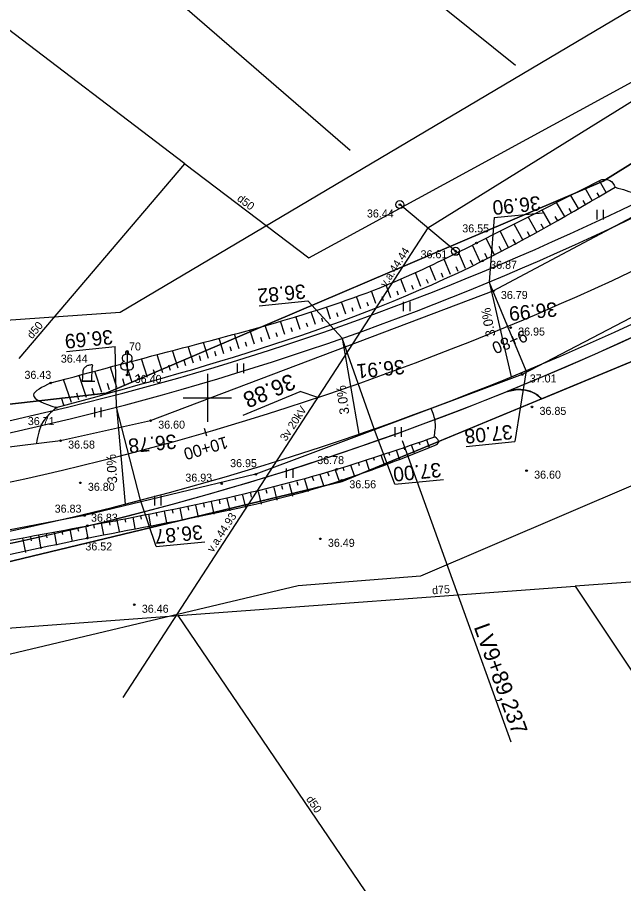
# Model space of a CAD drawing. Extents: x 469981 to 472086, y 246785 to 247785.
# Drawn here: x 471088.1 to 471126, y 247169.7 to 247223.8 of the extents above; entities that cross this region are included whole.
import ezdxf

# ---------------------------------------------------------------- set-up
doc = ezdxf.new("R2010")
doc.units = 0
for name, color, linetype in [('0_922', 7, 'Continuous'), ('0_Asfalta_mala', 7, 'Continuous'), ('0_Asfalta_Nomale', 7, 'Continuous'), ('0_Ruut_Braukt', 7, 'Continuous'), ('0_Ruut_nomale', 7, 'Continuous'), ('0_Ruutojums_Nobrauktuves_pieslegumi', 7, 'Continuous'), ('0_vertikals', 7, 'Continuous'), ('0_Vertikals_SavietotieInztikli', 7, 'Continuous'), ('0_vertkals_cipari', 7, 'Continuous'), ('21', 7, 'Continuous'), ('5_patagas', 7, 'Continuous'), ('6_piketaza', 7, 'Continuous'), ('CELI_CMAL_####_####_#', 7, 'Continuous'), ('DREN_VADP_####_####_#', 7, 'Continuous'), ('DREN_VADP_####_TKST_#', 7, 'Continuous'), ('DREN_VADP_KLKT_####_#', 7, 'Continuous'), ('DREN_VADP_KLKT_TKST_#', 7, 'Continuous'), ('ELEK_ELEM_####_####_#', 7, 'Continuous'), ('ELEK_SAVL_####_####_#', 7, 'Continuous'), ('ELEK_VADV_VSPR_####_#', 7, 'Continuous'), ('ELEK_VADV_VSPR_TKST_#', 7, 'Continuous'), ('GEOD_ELEM_####_####_#', 7, 'Continuous'), ('RAMI_UZMR_####_####_#', 7, 'Continuous'), ('RELJ_AATZ_####_TKST_#', 7, 'Continuous'), ('RELJ_ELEM_####_####_#', 7, 'Continuous'), ('RELJ_NOGA_####_####_#', 7, 'Continuous'), ('RELJ_NOGL_####_####_#', 7, 'Continuous'), ('ROBZ_IERR_####_####_#', 7, 'Continuous'), ('ROBZ_PROJ_####_####_#', 7, 'Continuous'), ('ROBZ_UZMR_####_####_#', 7, 'Continuous'), ('TERT_DIAM_####_TKST_#', 7, 'Continuous'), ('TERT_ELEM_####_####_#', 7, 'Continuous'), ('TERT_KONT_####_####_#', 7, 'Continuous')]:
    doc.layers.add(name, color=color, linetype=linetype)

msp = doc.modelspace()

# ---------------------------------------------------------------- linework, layer by layer
at = {"layer": '0_922'}
msp.add_arc((471049.697, 247370.7), 180, 277.44649, 302.18491, dxfattribs=at)
at = {"layer": '0_Asfalta_mala'}
for radius in [177, 183]:
    msp.add_arc((471049.697, 247370.7), radius, 277.44649, 302.18491, dxfattribs=at)
at = {"layer": '0_Asfalta_Nomale'}
for centre, radius, start, end in [((471049.697, 247370.7), 176.25, 277.44649, 302.18491), ((471049.697, 247370.7), 183.75, 277.44649, 292.06313), ((471119.477, 247198.533), 2, 45.236, 112.0499)]:
    msp.add_arc(centre, radius, start, end, dxfattribs=at)
at = {"layer": '0_Ruut_Braukt'}
for radius in [177, 183]:
    msp.add_arc((471049.697, 247370.7), radius, 277.44649, 302.18491, dxfattribs=at)
at = {"layer": '0_Ruut_nomale'}
for radius in [176.25, 177, 183, 183.75]:
    msp.add_arc((471049.697, 247370.7), radius, 277.44649, 302.18491, dxfattribs=at)
at = {"layer": '0_Ruutojums_Nobrauktuves_pieslegumi'}
msp.add_lwpolyline([(471126.647, 247202.343), (471126.642, 247202.698), (471126.793, 247203.326), (471127.142, 247203.879), (471127.778, 247204.365), (471126.081, 247203.579), (471124.175, 247202.721), (471122.812, 247202.123), (471120.922, 247201.316), (471118.719, 247200.406), (471119.354, 247200.529), (471119.871, 247200.494), (471120.234, 247200.385), (471120.541, 247200.227), (471120.886, 247199.953)], close=True, dxfattribs=at)
at = {"layer": '0_vertikals'}
for p, q in [((471117.907, 247211.264), (471117.603, 247207.245)), ((471117.907, 247211.264), (471120.938, 247211.569)), ((471103.241, 247205.754), (471106.272, 247206.059)), ((471108.421, 247203.726), (471106.272, 247206.059)), ((471091.204, 247202.907), (471094.236, 247203.211)), ((471094.32, 247199.417), (471094.236, 247203.211)), ((471119.905, 247201.704), (471119.194, 247197.275)), ((471111.706, 247194.605), (471110.411, 247198.066)), ((471116.163, 247196.971), (471119.194, 247197.275)), ((471111.706, 247194.605), (471114.737, 247194.909)), ((471096.812, 247190.713), (471095.832, 247193.611)), ((471096.812, 247190.713), (471099.844, 247191.018))]:
    msp.add_line(p, q, dxfattribs=at)
for points in [[(471117.603, 247207.245), (471118.981, 247201.322), (471119.905, 247201.704)], [(471108.421, 247203.726), (471109.467, 247197.736), (471110.411, 247198.066)], [(471094.32, 247199.417), (471094.864, 247193.361), (471095.832, 247193.611)]]:
    msp.add_lwpolyline(points, close=True, dxfattribs=at)
at = {"layer": '0_Vertikals_SavietotieInztikli'}
for p in [(471102.247, 247198.915), (471106.891, 247200.028)]:
    msp.add_line(p, (471105.797, 247200.401), dxfattribs=at)
at = {"layer": '21'}
msp.add_arc((471049.697, 247370.7), 180, 277.44649, 302.18491, dxfattribs=at)
at = {"layer": '5_patagas'}
msp.add_lwpolyline([(471112.166, 247197.334), (471118.946, 247178.518)], dxfattribs=at)
at = {"layer": '6_piketaza'}
for points in [[(471118.85, 247204.243), (471118.658, 247204.705)], [(471099.966, 247197.602), (471099.827, 247198.082)]]:
    msp.add_lwpolyline(points, dxfattribs=at)
at = {"layer": 'CELI_CMAL_####_####_#'}
for points in [[(471014.161, 247188.048), (471038.308, 247191.645), (471077.61, 247195.71), (471090.836, 247197.337), (471096.461, 247198.582), (471117.856, 247206.682), (471130.197, 247213.261), (471151.631, 247225.738), (471175.407, 247239.608), (471196.168, 247252.49), (471217.229, 247265.52), (471244.784, 247283.359), (471266.102, 247296.914), (471293.433, 247314.365), (471318.262, 247330.084), (471336.637, 247341.969), (471339.45, 247343.841), (471340.412, 247346.293), (471340.291, 247349.818), (471339.894, 247353.24), (471336.901, 247360.015), (471333.813, 247367.721)], [(471347.348, 247327.622), (471345.475, 247334.467), (471344.349, 247336.664), (471343.67, 247337.19), (471342.054, 247337.492), (471341.155, 247337.494), (471339.762, 247336.569), (471318.941, 247323.623), (471297.221, 247309.64), (471268.834, 247291.51), (471247.888, 247278.119), (471219.179, 247259.989), (471200.048, 247247.93), (471177.515, 247234.149), (471154.773, 247220.961), (471131.272, 247207.521), (471119.66, 247201.466), (471103.03, 247195.231), (471092.329, 247192.658), (471077.436, 247189.782), (471058.729, 247187.944), (471037.006, 247184.759), (471015.923, 247182.598), (470992.26, 247181.035)]]:
    msp.add_lwpolyline(points, dxfattribs=at)
at = {"layer": 'DREN_VADP_####_####_#'}
for points in [[(471093.793, 247241.252), (471119.237, 247220.794)], [(471098.595, 247214.62), (471106.329, 247208.745), (471138.491, 247226.277), (471152.344, 247233.828)], [(471088.246, 247202.471), (471098.595, 247214.62)], [(471151.231, 247181.956), (471145.953, 247189.907), (471122.964, 247188.241)], [(471122.964, 247188.241), (471132.872, 247173.374)], [(471113.256, 247164.203), (471098.172, 247186.404)]]:
    msp.add_lwpolyline(points, dxfattribs=at)
at = {"layer": 'DREN_VADP_KLKT_####_#'}
for points in [[(471108.928, 247215.461), (471082.698, 247238.164)], [(471098.595, 247214.62), (471086.597, 247223.736), (471071.652, 247235.09)], [(471004.84, 247177.619), (471029.945, 247181.347), (471052.991, 247183.055), (471075.414, 247184.717), (471098.172, 247186.404), (471122.964, 247188.241)]]:
    msp.add_lwpolyline(points, dxfattribs=at)
at = {"layer": 'ELEK_ELEM_####_####_#'}
for centre in [(471112.022, 247212.08), (471115.502, 247209.16)]:
    msp.add_circle(centre, 0.25, dxfattribs=at)
at = {"layer": 'ELEK_SAVL_####_####_#'}
msp.add_line((471115.502, 247209.16), (471112.022, 247212.08), dxfattribs=at)
at = {"layer": 'ELEK_VADV_VSPR_####_#'}
for q in [(471169.047, 247244.988), (471094.727, 247181.28)]:
    msp.add_line((471113.762, 247210.62), q, dxfattribs=at)
at = {"layer": 'GEOD_ELEM_####_####_#'}
for p, q in [((471100, 247201.5), (471100, 247200)), ((471098.5, 247200), (471100, 247200)), ((471100, 247200), (471100, 247198.5)), ((471100, 247200), (471101.5, 247200))]:
    msp.add_line(p, q, dxfattribs=at)
at = {"layer": 'RAMI_UZMR_####_####_#'}
for points in [[(471010.572, 247199.465), (471044.448, 247201.846), (471094.566, 247205.368), (471219.251, 247279.294), (471287.982, 247320.045), (471329.582, 247346.385), (471332.466, 247352.407), (471329.951, 247358.592), (471331.784, 247361.204), (471339.558, 247364.746), (471343.514, 247360.959), (471346.629, 247357.978), (471355.9, 247363.1), (471457.4, 247429.3)], [(471380.292, 247353.371), (471352.036, 247335.759), (471352.913, 247327.325), (471347.47, 247325.392), (471345.187, 247325.919), (471342.905, 247329.082), (471319.551, 247313.443), (471222.661, 247251.69), (471157.352, 247211.35), (471144.207, 247202.916), (471131.364, 247196.59), (471113.303, 247188.858), (471105.677, 247188.256), (471083.576, 247183.01), (471075.205, 247182.665), (471043.397, 247175.418), (471016.707, 247172.079), (470997.217, 247171.376)]]:
    msp.add_lwpolyline(points, dxfattribs=at)
at = {"layer": 'RELJ_ELEM_####_####_#'}
for centre in [(471112.022, 247212.08), (471116.807, 247209.683), (471115.502, 247209.16), (471117.19, 247208.567), (471117.856, 247206.682), (471118.936, 247204.398), (471094.992, 247201.437), (471119.66, 247201.466), (471090.221, 247200.936), (471090.563, 247199.396), (471120.27, 247199.442), (471096.461, 247198.582), (471090.836, 247197.337), (471108.077, 247195.543), (471119.933, 247195.459), (471103.03, 247195.231), (471108.392, 247194.857), (471092.068, 247194.698), (471100.896, 247194.639), (471092.329, 247192.658), (471092.52, 247192.014), (471092.506, 247191.243), (471107.056, 247191.2), (471095.436, 247187.08)]:
    msp.add_circle(centre, 0.05, dxfattribs=at)
at = {"layer": 'RELJ_NOGA_####_####_#'}
for p, q in [((471124.902, 247212.844), (471124.49, 247213.568)), ((471123.175, 247211.836), (471122.689, 247212.656)), ((471124.036, 247212.344), (471123.587, 247213.111)), ((471124.468, 247212.596), (471124.339, 247212.819)), ((471125.338, 247213.09), (471125.337, 247213.09)), ((471122.314, 247211.327), (471121.795, 247212.204)), ((471123.605, 247212.091), (471123.464, 247212.328)), ((471121.453, 247210.818), (471120.906, 247211.754)), ((471122.745, 247211.581), (471122.594, 247211.836)), ((471120.587, 247210.318), (471120.025, 247211.308)), ((471121.884, 247211.072), (471121.723, 247211.343)), ((471119.715, 247209.83), (471119.15, 247210.865)), ((471121.021, 247210.567), (471120.854, 247210.856)), ((471117.937, 247208.913), (471117.421, 247209.991)), ((471118.832, 247209.36), (471118.28, 247210.425)), ((471120.152, 247210.072), (471119.982, 247210.376)), ((471117.029, 247208.495), (471116.559, 247209.554)), ((471118.386, 247209.133), (471118.225, 247209.456)), ((471119.275, 247209.592), (471119.106, 247209.908)), ((471116.112, 247208.096), (471115.678, 247209.11)), ((471117.485, 247208.701), (471117.336, 247209.022)), ((471115.191, 247207.707), (471114.791, 247208.671)), ((471116.571, 247208.294), (471116.435, 247208.606)), ((471113.336, 247206.96), (471112.997, 247207.825)), ((471114.265, 247207.329), (471113.898, 247208.241)), ((471114.728, 247207.517), (471114.613, 247207.798)), ((471115.652, 247207.9), (471115.527, 247208.197)), ((471112.403, 247206.6), (471112.087, 247207.426)), ((471113.801, 247207.143), (471113.695, 247207.409)), ((471111.466, 247206.248), (471111.17, 247207.047)), ((471112.87, 247206.779), (471112.772, 247207.032)), ((471109.586, 247205.568), (471109.314, 247206.339)), ((471110.527, 247205.905), (471110.246, 247206.685)), ((471110.997, 247206.076), (471110.91, 247206.312)), ((471111.935, 247206.423), (471111.844, 247206.667)), ((471107.696, 247204.915), (471107.433, 247205.69)), ((471108.642, 247205.238), (471108.375, 247206.008)), ((471109.114, 247205.403), (471109.034, 247205.633)), ((471110.057, 247205.736), (471109.974, 247205.968)), ((471105.798, 247204.282), (471105.533, 247205.09)), ((471106.748, 247204.596), (471106.486, 247205.385)), ((471108.169, 247205.076), (471108.09, 247205.307)), ((471104.847, 247203.973), (471104.579, 247204.805)), ((471106.273, 247204.439), (471106.194, 247204.678)), ((471107.222, 247204.755), (471107.143, 247204.989)), ((471101.989, 247203.062), (471101.696, 247203.993)), ((471102.943, 247203.363), (471102.659, 247204.258)), ((471103.895, 247203.666), (471103.62, 247204.528)), ((471104.371, 247203.819), (471104.29, 247204.073)), ((471105.323, 247204.127), (471105.243, 247204.373)), ((471100.08, 247202.464), (471099.765, 247203.474)), ((471101.035, 247202.762), (471100.731, 247203.732)), ((471102.466, 247203.212), (471102.379, 247203.486)), ((471103.419, 247203.514), (471103.335, 247203.778)), ((471098.172, 247201.867), (471097.83, 247202.96)), ((471099.126, 247202.165), (471098.797, 247203.217)), ((471101.512, 247202.912), (471101.422, 247203.197)), ((471096.264, 247201.267), (471095.891, 247202.444)), ((471097.217, 247201.568), (471096.861, 247202.702)), ((471099.603, 247202.315), (471099.507, 247202.624)), ((471100.558, 247202.613), (471100.465, 247202.91)), ((471094.359, 247200.658), (471093.948, 247201.928)), ((471095.311, 247200.964), (471094.921, 247202.186)), ((471097.694, 247201.718), (471097.59, 247202.052)), ((471098.649, 247202.016), (471098.548, 247202.338)), ((471092.458, 247200.036), (471092.001, 247201.41)), ((471093.407, 247200.349), (471092.977, 247201.669)), ((471095.787, 247201.116), (471095.672, 247201.476)), ((471096.74, 247201.418), (471096.631, 247201.764)), ((471091.509, 247199.719), (471091.027, 247201.15)), ((471093.883, 247200.504), (471093.757, 247200.893)), ((471094.834, 247200.812), (471094.715, 247201.185)), ((471091.983, 247199.878), (471091.843, 247200.299)), ((471092.932, 247200.193), (471092.799, 247200.597)), ((471091.036, 247199.558), (471090.887, 247199.997)), ((471090.563, 247199.396), (471090.563, 247199.397)), ((471114.16, 247197.552), (471114.16, 247197.552)), ((471112.735, 247197.082), (471112.912, 247196.548)), ((471113.21, 247197.238), (471113.261, 247197.084)), ((471113.685, 247197.395), (471113.849, 247196.899)), ((471110.836, 247196.454), (471111.037, 247195.847)), ((471111.311, 247196.611), (471111.369, 247196.434)), ((471111.786, 247196.768), (471111.974, 247196.197)), ((471112.261, 247196.925), (471112.315, 247196.759)), ((471109.412, 247195.984), (471109.478, 247195.785)), ((471109.887, 247196.141), (471110.1, 247195.496)), ((471110.361, 247196.298), (471110.423, 247196.11)), ((471107.512, 247195.36), (471107.582, 247195.139)), ((471107.987, 247195.514), (471108.223, 247194.794)), ((471108.462, 247195.67), (471108.532, 247195.46)), ((471108.937, 247195.827), (471109.162, 247195.145)), ((471106.076, 247194.926), (471106.301, 247194.152)), ((471106.556, 247195.066), (471106.624, 247194.837)), ((471107.034, 247195.211), (471107.265, 247194.459)), ((471103.661, 247194.28), (471103.719, 247194.043)), ((471104.146, 247194.402), (471104.347, 247193.611)), ((471104.63, 247194.528), (471104.692, 247194.291)), ((471105.113, 247194.657), (471105.327, 247193.87)), ((471105.595, 247194.789), (471105.66, 247194.555)), ((471101.226, 247193.714), (471101.395, 247192.943)), ((471101.714, 247193.822), (471101.766, 247193.589)), ((471102.202, 247193.932), (471102.382, 247193.15)), ((471102.689, 247194.046), (471102.744, 247193.809)), ((471103.175, 247194.161), (471103.366, 247193.372)), ((471098.778, 247193.205), (471098.822, 247192.984)), ((471099.269, 247193.304), (471099.419, 247192.559)), ((471099.758, 247193.403), (471099.805, 247193.178)), ((471100.248, 247193.505), (471100.407, 247192.746)), ((471100.737, 247193.609), (471100.786, 247193.379)), ((471095.832, 247192.639), (471095.872, 247192.426)), ((471096.324, 247192.731), (471096.459, 247192.018)), ((471096.815, 247192.824), (471096.856, 247192.609)), ((471097.306, 247192.918), (471097.444, 247192.198)), ((471097.797, 247193.013), (471097.839, 247192.795)), ((471098.288, 247193.108), (471098.431, 247192.377)), ((471093.375, 247192.177), (471093.512, 247191.455)), ((471093.867, 247192.27), (471093.907, 247192.055)), ((471094.358, 247192.362), (471094.492, 247191.65)), ((471094.849, 247192.454), (471094.889, 247192.241)), ((471095.341, 247192.546), (471095.474, 247191.837)), ((471090.429, 247191.61), (471090.585, 247190.808)), ((471090.92, 247191.705), (471090.966, 247191.47)), ((471091.411, 247191.8), (471091.56, 247191.033)), ((471091.902, 247191.895), (471091.946, 247191.669)), ((471092.393, 247191.99), (471092.536, 247191.249)), ((471092.884, 247192.084), (471092.926, 247191.865)), ((471088.466, 247191.23), (471088.637, 247190.347)), ((471088.957, 247191.325), (471089.007, 247191.066)), ((471089.448, 247191.42), (471089.611, 247190.579)), ((471089.939, 247191.515), (471089.986, 247191.269))]:
    msp.add_line(p, q, dxfattribs=at)
for points in [[(471090.563, 247199.396), (471117.19, 247208.567), (471125.472, 247213.165)], [(471037.008, 247183.786), (471077.386, 247189.324), (471092.52, 247192.014), (471108.077, 247195.543), (471114.215, 247197.57)]]:
    msp.add_spline(points, degree=3, dxfattribs=at)
at = {"layer": 'RELJ_NOGL_####_####_#'}
for points in [[(471090.221, 247200.936), (471098.006, 247203.007), (471112.108, 247207.435), (471117.36, 247209.96), (471124.639, 247213.643)], [(471124.639, 247213.643), (471125.14, 247213.594), (471125.472, 247213.165)], [(471090.221, 247200.936), (471089.14, 247200.19), (471090.563, 247199.396)], [(471114.235, 247197.043), (471114.448, 247197.245), (471114.215, 247197.57)], [(471036.91, 247182.787), (471077.214, 247187.994), (471092.506, 247191.243), (471108.392, 247194.857), (471114.235, 247197.043)]]:
    msp.add_spline(points, degree=3, dxfattribs=at)
at = {"layer": 'ROBZ_IERR_####_####_#'}
msp.add_lwpolyline([(471513.259, 247488.166), (471524.883, 247464.852), (471341.261, 247348.2), (471124.72, 247213.54), (471093.674, 247200.298), (471050.609, 247195.379), (471001.509, 247189.266), (470977.922, 247249.601)], dxfattribs=at)
at = {"layer": 'ROBZ_PROJ_####_####_#'}
for points in [[(470613.752, 247179.765), (470688.303, 247197.106), (470783.692, 247219.293), (470809.088, 247224.67), (470845.751, 247226.447), (470876.169, 247225.296), (470921.641, 247209.731), (470967.353, 247194.084), (470989.48, 247188.802), (471001.509, 247189.266), (471050.609, 247195.379), (471093.674, 247200.298), (471124.72, 247213.54), (471341.261, 247348.2), (471524.883, 247464.852)], [(471398.351, 247372.094), (471346.741, 247338.478), (471133.176, 247205.05), (471108.425, 247194.786), (471087.339, 247189.709), (471023.306, 247181.157), (470962.604, 247185.245), (470905.63, 247205.857), (470878.75, 247214.454), (470852.344, 247217.039), (470815.743, 247215.147), (470778.583, 247209.26), (470718.669, 247194.633), (470636.973, 247175.147), (470468.364, 247124.23), (470431.624, 247112.202), (470396.219, 247097.502), (470371.503, 247083.47), (470275.956, 246992.729), (470152.342, 246907.761), (470066.737, 246851.23)]]:
    msp.add_lwpolyline(points, dxfattribs=at)
at = {"layer": 'ROBZ_UZMR_####_####_#'}
msp.add_lwpolyline([(470963.76, 247148.152), (470962.604, 247185.245), (471023.306, 247181.157), (471087.339, 247189.709), (471108.425, 247194.786), (471133.176, 247205.05), (471165.539, 247180.17)], dxfattribs=at)
at = {"layer": 'TERT_ELEM_####_####_#'}
for p, q in [((471124.337, 247211.158), (471124.337, 247211.758)), ((471124.737, 247211.158), (471124.737, 247211.758)), ((471112.255, 247205.412), (471112.255, 247206.012)), ((471112.655, 247205.412), (471112.655, 247206.012)), ((471092.785, 247201.055), (471092.819, 247201.92)), ((471101.886, 247201.553), (471101.886, 247202.153)), ((471102.286, 247201.553), (471102.286, 247202.153)), ((471092.216, 247201.628), (471092.185, 247201.055)), ((471094.992, 247201.784), (471094.992, 247201.437)), ((471094.992, 247201.437), (471095.192, 247201.437)), ((471092.785, 247201.055), (471092.185, 247201.055)), ((471092.185, 247201.055), (471092.485, 247201.055)), ((471092.485, 247201.055), (471092.785, 247201.055)), ((471092.785, 247201.055), (471092.985, 247201.055)), ((471092.974, 247198.809), (471092.974, 247199.409)), ((471093.374, 247198.809), (471093.374, 247199.409)), ((471111.719, 247197.572), (471111.719, 247198.172)), ((471112.119, 247197.572), (471112.119, 247198.172)), ((471104.95, 247194.999), (471104.95, 247195.599)), ((471105.35, 247194.999), (471105.35, 247195.599)), ((471096.723, 247193.284), (471096.723, 247193.884)), ((471097.123, 247193.284), (471097.123, 247193.884))]:
    msp.add_line(p, q, dxfattribs=at)
for points in [[(471094.992, 247202.937), (471094.992, 247201.784)], [(471095.082, 247202.705), (471095.081, 247202.706)]]:
    msp.add_lwpolyline(points, dxfattribs=at)
for centre, major_axis, ratio, start_param, end_param in [((471094.992, 247202.787), (0, -0.15), 0.707107, 3.14537, 5.287485), ((471094.992, 247202.787), (0, -0.15), 0.707107, 0.995701, 3.137816), ((471094.864, 247202.492), (-0.039, -0.212), 0.861323, 3.141593, 6.283185), ((471095.12, 247202.492), (0.039, -0.212), 0.861323, 0, 3.141593), ((471094.902, 247202.03), (0.307, 0.095), 0.814445, 1.570796, 4.752015), ((471095.082, 247202.03), (-0.307, 0.095), 0.814445, 1.531171, 4.712389)]:
    msp.add_ellipse(centre, major_axis=major_axis, ratio=ratio, start_param=start_param, end_param=end_param, dxfattribs=at)
msp.add_spline([(471092.819, 247201.92), (471092.823, 247201.951), (471092.826, 247201.962), (471092.841, 247202.024), (471092.811, 247202.059), (471092.689, 247202.053), (471092.585, 247202.035), (471092.479, 247201.996), (471092.414, 247201.952), (471092.339, 247201.888), (471092.259, 247201.79), (471092.228, 247201.701), (471092.216, 247201.627)], degree=3, dxfattribs=at)
at = {"layer": 'TERT_KONT_####_####_#'}
for points in [[(471125.472, 247213.165), (471126.806, 247212.721), (471127.982, 247212.161)], [(471090.563, 247199.396), (471089.716, 247198.468), (471089.324, 247197.18)], [(471114.16, 247197.552), (471114.236, 247198.473), (471113.984, 247199.341)]]:
    msp.add_spline(points, degree=3, dxfattribs=at)

# ---------------------------------------------------------------- texts
at = {"layer": '0_Vertikals_SavietotieInztikli'}
msp.add_text('36.88', height=1, rotation=202.7195, dxfattribs=at).set_placement((471105.225, 247201.549))
at = {"layer": '0_vertkals_cipari'}
for s, height, rotation, p in [('36.90', 0.9, 185.7316, (471120.762, 247212.622)), ('36.82', 0.9, 185.7316, (471106.096, 247207.112)), ('3.0%', 0.5993, 100.7007, (471118.001, 247203.881)), ('36.99', 0.9, 185.7316, (471121.797, 247205.996)), ('36.69', 0.9, 185.7316, (471094.06, 247204.265)), ('36.91', 0.9, 185.7316, (471112.278, 247202.4)), ('3.0%', 0.5993, 97.5172, (471108.869, 247199.007)), ('37.08', 0.9, 185.7316, (471119.018, 247198.329)), ('36.78', 0.9, 185.7316, (471098.026, 247197.738)), ('3.0%', 0.5993, 92.7429, (471094.374, 247194.678)), ('37.00', 0.9, 185.7316, (471114.561, 247195.963)), ('36.87', 0.9, 185.7316, (471099.667, 247192.072))]:
    msp.add_text(s, height=height, rotation=rotation, dxfattribs=at).set_placement(p)
at = {"layer": '5_patagas'}
msp.add_text('LV9+89,237', height=1, rotation=289.8157, dxfattribs=at).set_placement((471116.626, 247185.694))
at = {"layer": '6_piketaza'}
for s, rotation, p in [('9+80', 202.56, (471119.781, 247204.278)), ('10+00', 196.1938, (471101.162, 247197.611))]:
    msp.add_text(s, height=0.75, rotation=rotation, dxfattribs=at).set_placement(p)
at = {"layer": 'DREN_VADP_####_TKST_#'}
for rotation, p in [(322.7753, (471101.811, 247212.366)), (49.5716, (471089.057, 247203.655)), (304.1948, (471106.141, 247174.942))]:
    msp.add_text('d50', height=0.5, rotation=rotation, dxfattribs=at).set_placement(p)
at = {"layer": 'DREN_VADP_KLKT_TKST_#'}
msp.add_text('d75', height=0.5, rotation=4.2375, dxfattribs=at).set_placement((471114.051, 247187.731))
at = {"layer": 'ELEK_VADV_VSPR_TKST_#'}
for s, rotation, p in [('v.a.44.44', 57.0257, (471111.159, 247206.883)), ('3v 20kV', 57.0257, (471104.914, 247197.257)), ('v.a.44.93', 57.0799, (471100.354, 247190.315))]:
    msp.add_text(s, height=0.5, rotation=rotation, dxfattribs=at).set_placement(p)
at = {"layer": 'RELJ_AATZ_####_TKST_#'}
for s, p in [('36.44', (471109.966, 247211.273)), ('36.55', (471115.919, 247210.343)), ('36.61', (471113.316, 247208.727)), ('36.87', (471117.663, 247208.067)), ('36.79', (471118.33, 247206.182)), ('36.95', (471119.41, 247203.898)), ('36.44', (471090.851, 247202.206)), ('36.43', (471088.581, 247201.193)), ('36.40', (471095.465, 247200.937)), ('37.01', (471120.133, 247200.966)), ('36.85', (471120.743, 247198.942)), ('36.71', (471088.791, 247198.305)), ('36.60', (471096.934, 247198.082)), ('36.58', (471091.309, 247196.837)), ('36.95', (471101.423, 247195.677)), ('36.78', (471106.863, 247195.867)), ('36.60', (471120.406, 247194.959)), ('36.93', (471098.627, 247194.771)), ('36.56', (471108.866, 247194.357)), ('36.80', (471092.541, 247194.198)), ('36.83', (471090.467, 247192.834)), ('36.83', (471092.736, 247192.271)), ('36.49', (471107.53, 247190.7)), ('36.52', (471092.385, 247190.473)), ('36.46', (471095.909, 247186.58))]:
    msp.add_text(s, height=0.5, dxfattribs=at).set_placement(p)
at = {"layer": 'TERT_DIAM_####_TKST_#'}
msp.add_text('70', height=0.5, dxfattribs=at).set_placement((471095.11, 247202.966))

doc.saveas('drawing.dxf')
